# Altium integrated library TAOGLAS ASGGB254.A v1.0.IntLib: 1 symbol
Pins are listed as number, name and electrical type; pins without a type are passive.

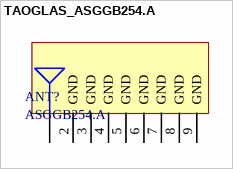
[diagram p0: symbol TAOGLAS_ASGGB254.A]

## TAOGLAS_ASGGB254.A
designator ANT?, comment ASGGB254.A
GPS/GLONASS/BeiDou/Galileo SMD Active Patch with Embedded Active Circuitry; ComponentLibStatus: Created; MFG: Taoglas; Temp_Low: -40C; Temp_High: +85C
footprint TAOGLAS_ASGGB254.A (GPS/GLONASS/BeiDou/Galileo SMD Active Patch with Embedded Active Circuitry)
pins: 1 RF, 2 GND, 3 GND, 4 GND, 5 GND, 6 GND, 7 GND, 8 GND, 9 GND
